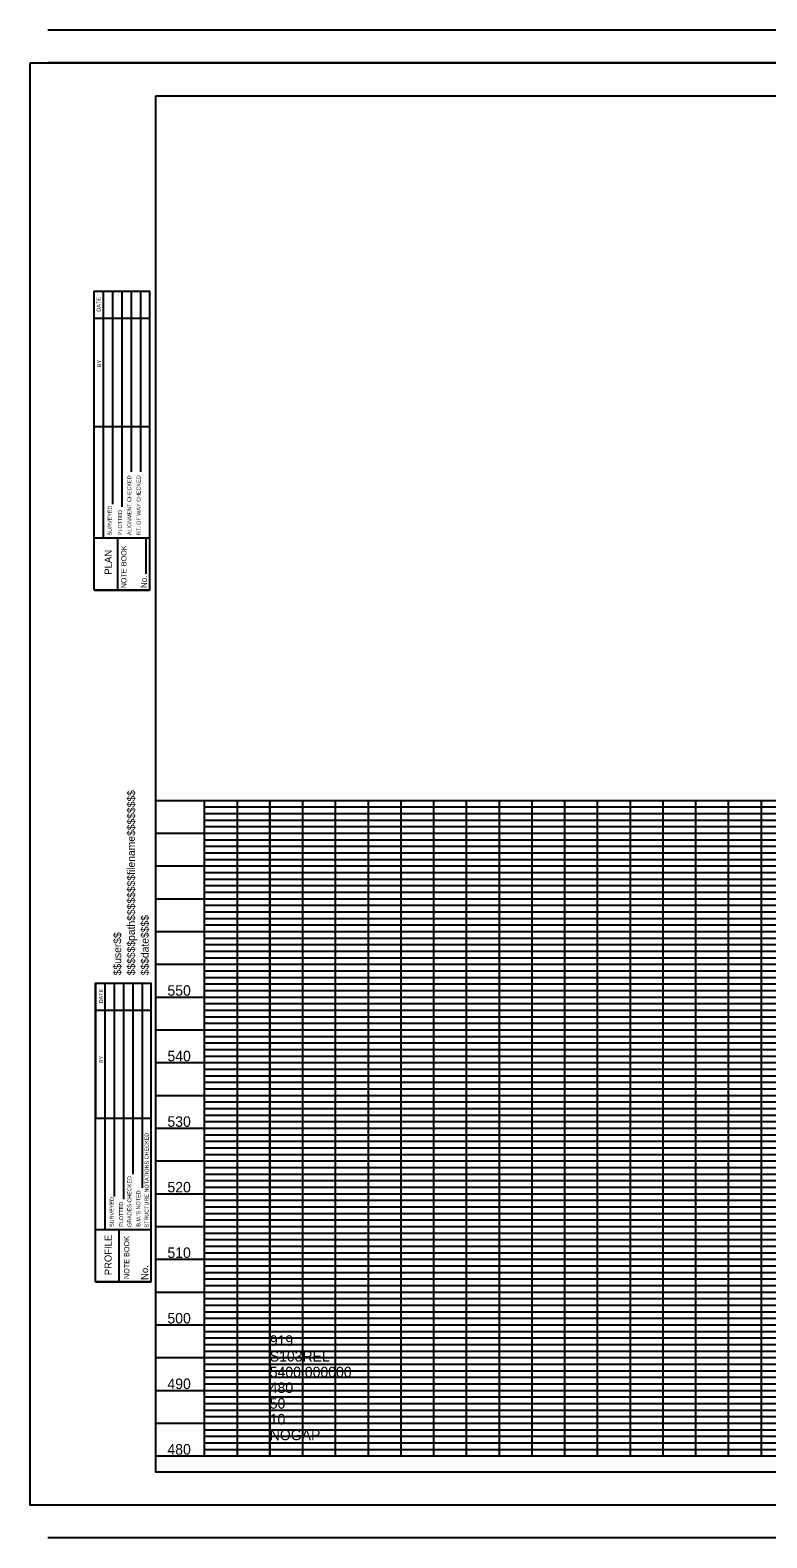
# Model space of a CAD drawing. Extents: x 49817 to 52197, y 49938 to 51088.
# Drawn here: x 49817 to 50379, y 49938 to 51088 of the extents above; entities that cross this region are included whole.
import ezdxf

# ---------------------------------------------------------------- set-up
doc = ezdxf.new("R2010")
doc.units = 0
for name, color, linetype in [('RD_DDB_ElevTX', 7, 'Continuous'), ('RD_GPK_Profile_Cell', 7, 'Continuous'), ('RD_SHT_Bndy', 7, 'Continuous'), ('RD_SHT_ID', 7, 'Continuous'), ('RD_SHT_Iplotshp', 7, 'Continuous'), ('RD_SHT_MjGrid', 7, 'Continuous'), ('RD_SHT_MnGrid', 7, 'Continuous'), ('RD_SHT_SubGrid', 7, 'Continuous'), ('RD_SHT_TX', 7, 'Continuous')]:
    doc.layers.add(name, color=color, linetype=linetype)

msp = doc.modelspace()

# ---------------------------------------------------------------- linework, layer by layer
at = {"layer": 'RD_GPK_Profile_Cell'}
for q in [(50000, 50500), (52196.9, 50000), (50000, 50000)]:
    msp.add_line((50000, 50000), q, dxfattribs=at)
at = {"layer": 'RD_SHT_Bndy'}
for p, q in [((51590.7, 51087.5), (49830.7, 51087.5)), ((51590.7, 51062.5), (49830.7, 51062.5)), ((49866.1, 50785.1), (49866.1, 50888.3)), ((49873.2, 50700.4), (49873.2, 50888.3)), ((49880.2, 50726), (49880.2, 50888.3)), ((49887.3, 50723.8), (49887.3, 50888.3)), ((49894.4, 50750.7), (49894.4, 50888.3)), ((49901.5, 50750.7), (49901.5, 50888.3)), ((49866.1, 50867.7), (49908.1, 50867.7)), ((49866.1, 50785.1), (49908.1, 50785.1)), ((49866.1, 50700.3), (49908.1, 50700.3)), ((49884.1, 50660.3), (49884.1, 50700.3)), ((49905.6, 50672.8), (49905.6, 50700.3)), ((49866.1, 50660.3), (49908.1, 50660.3)), ((49913, 50500), (51588, 50500)), ((49950, 50500), (49950, 50000)), ((49867.1, 50360.7), (49867.1, 50257.5)), ((49874.2, 50360.7), (49874.2, 50172.8)), ((49881.2, 50360.7), (49881.2, 50197.8)), ((49888.3, 50360.7), (49888.3, 50195.8)), ((49895.4, 50360.7), (49895.4, 50214.9)), ((49902.5, 50360.7), (49902.5, 50204.4)), ((49867.1, 50340.1), (49909.1, 50340.1)), ((49867.1, 50257.5), (49909.1, 50257.5)), ((49867.1, 50172.7), (49909.1, 50172.7)), ((49867.1, 50132.7), (49867.1, 50172.7)), ((49885.1, 50132.7), (49885.1, 50172.7)), ((49867.1, 50132.7), (49909.1, 50132.7)), ((49913, 50000), (51588, 50000)), ((51590.7, 49962.5), (49830.7, 49962.5)), ((51590.7, 49937.5), (49830.7, 49937.5))]:
    msp.add_line(p, q, dxfattribs=at)
for points in [[(49913.1, 51037.5), (51588, 51037.5), (51588, 49987.5), (49913.1, 49987.5)], [(49866.1, 50660.3), (49866.1, 50888.3), (49908.1, 50888.3), (49908.1, 50660.3)], [(49867.1, 50132.7), (49867.1, 50360.7), (49909.1, 50360.7), (49909.1, 50132.7)]]:
    msp.add_lwpolyline(points, close=True, dxfattribs=at)
at = {"layer": 'RD_SHT_Iplotshp'}
msp.add_lwpolyline([(49817.1, 51062.5), (51613, 51062.5), (51613, 49962.5), (49817.1, 49962.5)], close=True, dxfattribs=at)
at = {"layer": 'RD_SHT_MjGrid'}
for p, q in [((50000, 50500), (50000, 50000)), ((50050, 50500), (50050, 50000)), ((50100, 50500), (50100, 50000)), ((50150, 50500), (50150, 50000)), ((50200, 50500), (50200, 50000)), ((50250, 50500), (50250, 50000)), ((50300, 50500), (50300, 50000)), ((50350, 50500), (50350, 50000)), ((49913, 50450), (51588, 50450)), ((49913, 50400), (51588, 50400)), ((49913, 50350), (51588, 50350)), ((49913, 50300), (51588, 50300)), ((49913, 50250), (51588, 50250)), ((49913, 50200), (51588, 50200)), ((49913, 50150), (51588, 50150)), ((49913, 50100), (51588, 50100)), ((49913, 50050), (51588, 50050))]:
    msp.add_line(p, q, dxfattribs=at)
at = {"layer": 'RD_SHT_MnGrid'}
for p, q in [((49975, 50500), (49975, 50000)), ((50025, 50500), (50025, 50000)), ((50075, 50500), (50075, 50000)), ((50125, 50500), (50125, 50000)), ((50175, 50500), (50175, 50000)), ((50225, 50500), (50225, 50000)), ((50275, 50500), (50275, 50000)), ((50325, 50500), (50325, 50000)), ((50375, 50500), (50375, 50000)), ((49913, 50475), (51588, 50475)), ((49913, 50425), (51588, 50425)), ((49913, 50375), (51588, 50375)), ((49913, 50325), (51588, 50325)), ((49913, 50275), (51588, 50275)), ((49913, 50225), (51588, 50225)), ((49913, 50175), (51588, 50175)), ((49913, 50125), (51588, 50125)), ((49913, 50075), (51588, 50075)), ((49913, 50025), (51588, 50025))]:
    msp.add_line(p, q, dxfattribs=at)
at = {"layer": 'RD_SHT_SubGrid'}
for p, q in [((49950.1, 50495), (51549.8, 50495)), ((49950.1, 50490), (51549.3, 50490)), ((49950.1, 50485), (51549.8, 50485)), ((49950.1, 50480), (51549.8, 50480)), ((49950.1, 50470), (51549.8, 50470)), ((49950.1, 50465), (51548.8, 50465)), ((49950.1, 50460), (51549.3, 50460)), ((49950.1, 50455), (51549.8, 50455)), ((49950.1, 50445), (51549.8, 50445)), ((49950.1, 50440), (51549.8, 50440)), ((49950.1, 50435), (51549.3, 50435)), ((49950.1, 50430), (51549.8, 50430)), ((49950.1, 50420), (51548.8, 50420)), ((49950.1, 50415), (51548.8, 50415)), ((49950.1, 50410), (51549.3, 50410)), ((49950.1, 50405), (51549.3, 50405)), ((49950.1, 50395), (51548.8, 50395)), ((49950.1, 50390), (51549.3, 50390)), ((49950.1, 50385), (51548.8, 50385)), ((49950.1, 50380), (51549.8, 50380)), ((49950.1, 50370), (51549.3, 50370)), ((49950.1, 50365), (51549.3, 50365)), ((49950.1, 50360), (51549.3, 50360)), ((49950.1, 50355), (51549.3, 50355)), ((49950.2, 50345), (51548.8, 50345)), ((49950.2, 50340), (51548.8, 50340)), ((49950.1, 50335), (51549.3, 50335)), ((49950.1, 50330), (51549.3, 50330)), ((49950.1, 50320), (51549.3, 50320)), ((49950.1, 50315), (51549.3, 50315)), ((49950.1, 50310), (51548.8, 50310)), ((49950.1, 50305), (51549.3, 50305)), ((49950.1, 50305), (51549.3, 50305)), ((49950.1, 50295), (51549.8, 50295)), ((49950.1, 50290), (51549.8, 50290)), ((49950.1, 50285), (51549.8, 50285)), ((49950.1, 50280), (51549.8, 50280)), ((49950.1, 50270), (51549.8, 50270)), ((49950.1, 50265), (51549.8, 50265)), ((49950.1, 50260), (51549.8, 50260)), ((49950.1, 50255), (51549.8, 50255)), ((49950.1, 50245), (51549.9, 50245)), ((49950.1, 50240), (51549.9, 50240)), ((49950.1, 50235), (51549.9, 50235)), ((49950.1, 50230), (51549.9, 50230)), ((49950.1, 50220), (51549.9, 50220)), ((49950.1, 50215), (51549.9, 50215)), ((49950.1, 50210), (51549.9, 50210)), ((49950.1, 50205), (51549.9, 50205)), ((49950.1, 50195), (51549.9, 50195)), ((49950.1, 50190), (51549.9, 50190)), ((49950.1, 50185), (51549.9, 50185)), ((49950.1, 50180), (51549.9, 50180)), ((49950.1, 50170), (51549.9, 50170)), ((49950.1, 50170), (51549.9, 50170)), ((49950.1, 50165), (51549.9, 50165)), ((49950.1, 50160), (51549.6, 50160)), ((49950.1, 50155), (51549.6, 50155)), ((49950.1, 50145), (51549.8, 50145)), ((49950.1, 50140), (51550, 50140)), ((49950.1, 50135), (51550, 50135)), ((49950.1, 50130), (51550, 50130)), ((49950.1, 50120), (51550, 50120)), ((49950.1, 50115), (51550, 50115)), ((49950.1, 50110), (51550, 50110)), ((49950.1, 50105), (51550, 50105)), ((49950.1, 50095), (51550, 50095)), ((49950.1, 50090), (51550, 50090)), ((49950.1, 50085), (51550, 50085)), ((49950.1, 50080), (51549.9, 50080)), ((49950.1, 50070), (51549.6, 50070)), ((49950.1, 50065), (51549.9, 50065)), ((49950.1, 50060), (51549.9, 50060)), ((49950.1, 50055), (51549.9, 50055)), ((49950.1, 50040), (51549.9, 50040)), ((49950.2, 50045), (51549.9, 50045)), ((49950.1, 50035), (51549.9, 50035)), ((49950.1, 50030), (51549.9, 50030)), ((49950.2, 50020), (51549.9, 50020)), ((49950.2, 50015), (51549.9, 50015)), ((49950.2, 50010), (51549.9, 50010)), ((49950.2, 50005), (51549.9, 50005))]:
    msp.add_line(p, q, dxfattribs=at)

# ---------------------------------------------------------------- texts
at = {"layer": 'RD_DDB_ElevTX'}
for s, p in [('550', (49921.9, 50351)), ('540', (49921.9, 50301)), ('530', (49921.9, 50251)), ('520', (49921.9, 50201)), ('510', (49921.9, 50151)), ('500', (49921.9, 50101)), ('490', (49921.9, 50051)), ('480', (49921.9, 50001))]:
    msp.add_text(s, height=8, dxfattribs=at).set_placement(p)
at = {"layer": 'RD_GPK_Profile_Cell'}
for s, p in [('919', (50000, 50084)), ('S103REL', (50000, 50072)), ('5400.000000', (50000, 50060)), ('480', (50000, 50048)), ('50', (50000, 50036)), ('10', (50000, 50024)), ('NOGAP', (50000, 50012))]:
    msp.add_text(s, height=8, dxfattribs=at).set_placement(p)
at = {"layer": 'RD_SHT_ID'}
for s, p in [('$$$$$$path$$$$$$$$filename$$$$$$$$', (49897.1, 50366.6)), ('$$$date$$$$', (49907.6, 50366.6)), ('$$user$$', (49886.6, 50366.6))]:
    msp.add_text(s, height=5.88, rotation=90, dxfattribs=at).set_placement(p)
at = {"layer": 'RD_SHT_TX'}
for s, height, p in [('DATE', 3, (49870.9, 50872.8)), ('BY', 3, (49871.3, 50830.5)), ('ALIGNMENT CHECKED', 3, (49894.3, 50702.3)), ('RT. OF WAY CHECKED', 3, (49901.4, 50702.4)), ('SURVEYED', 3, (49879.4, 50702.1)), ('PLOTTED', 3, (49887.2, 50702.3)), ('NOTE BOOK', 4, (49890.6, 50661.7)), ('PLAN', 5.4, (49879.3, 50672.2)), ('No.', 4.5, (49906.2, 50662)), ('DATE', 3, (49872.7, 50345.2)), ('BY', 3, (49872.7, 50299.5)), ('STRUCTURE NOTATIONS CHECKED', 3, (49907.5, 50174.2)), ('GRADES CHECKED', 3, (49894.4, 50174.6)), ("B.M.'S NOTED", 3, (49901.2, 50174.8)), ('SURVEYED', 3, (49880.9, 50174.6)), ('PLOTTED', 3, (49888, 50174.7)), ('PROFILE', 5.4, (49879.3, 50137.8)), ('NOTE BOOK', 4, (49892.8, 50134.9)), ('No.', 5.4, (49907.2, 50134.2))]:
    msp.add_text(s, height=height, rotation=90, dxfattribs=at).set_placement(p)

doc.saveas('drawing.dxf')
